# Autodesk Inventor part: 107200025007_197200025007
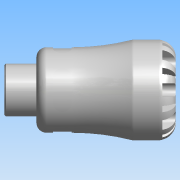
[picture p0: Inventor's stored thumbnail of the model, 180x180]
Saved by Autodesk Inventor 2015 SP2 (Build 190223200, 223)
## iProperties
Created: 2016-12
Part Number: 107200025007_197200025007
Material: PVC-Piping
Description: PLASSON MALE INTEGRAL BRASS THREAD 25X3/4" SERIES 1
Document SubType Name: Modeling
Designer: KIM
Mass: 61.7504 g
Surface Area: 140.097 cm^2
Volume: 44.1074 cm^3
Density: 1.4 g/cm^3
Appearance: Smooth - White
Author: KIM
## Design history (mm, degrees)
derived "1072.ipt"
feature "Solid1::1072.ipt"
tag "TaggingFeature1"
body "Solid1"
other parameters: "d1" = 20.16, "d2" = 25, "d3" = 31.25, "d4" = 47, "d6" = 48, "d8" = 39.95, "d13" = 6.3, "d14" = 6.3, "d15" = 0, "d17" = 360 deg, "d19" = 8 deg, "d20" = 0.5, "d21" = 0.5, "d22" = 8 deg, "d24" = 0, "d26" = 360 deg, "d32" = 4.7, "d33" = 4.7, "d34" = 24.658, "d38" = 15, "d39" = 0.73974, "d42" = 8.75, "d43" = 5.75, "d45" = 12.348, "d46" = 0, "d59" = 360 deg, "d61" = 7.4375, "d62" = 0.5, "d64" = 0, "d65" = 0.47, "d68" = 3.57143, "d_" = 25, "E_" = 47, "l_" = 48, "R_" = 24.658, "l_2" = 15, "d9" = 7.875, "d11" = 47, "d12" = 31.25
